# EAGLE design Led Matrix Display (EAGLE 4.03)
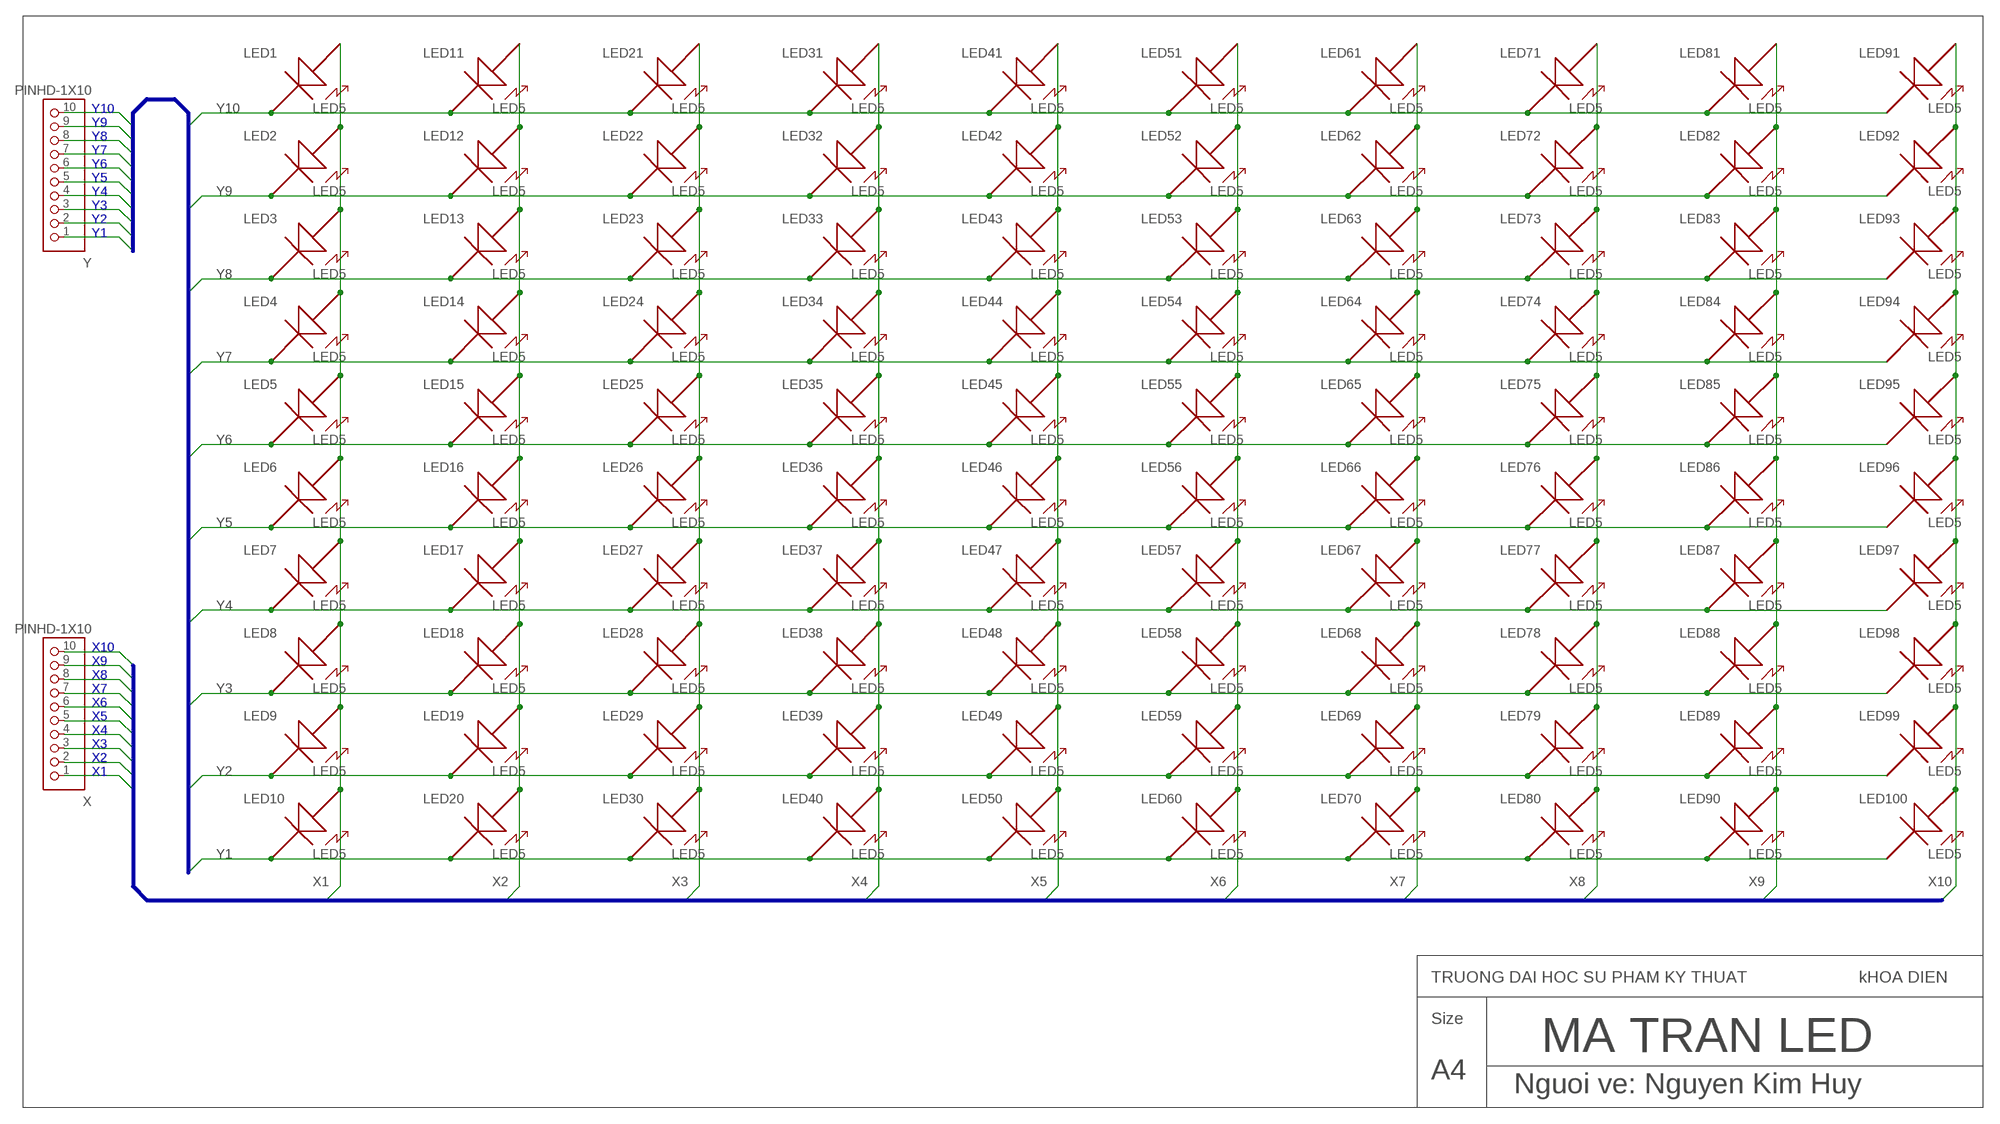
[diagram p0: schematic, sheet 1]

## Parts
LED1  LED5  [LED5]
LED2  LED5  [LED5]
LED3  LED5  [LED5]
LED4  LED5  [LED5]
LED5  LED5  [LED5]
LED6  LED5  [LED5]
LED7  LED5  [LED5]
LED8  LED5  [LED5]
LED9  LED5  [LED5]
LED10  LED5  [LED5]
LED11  LED5  [LED5]
LED12  LED5  [LED5]
LED13  LED5  [LED5]
LED14  LED5  [LED5]
LED15  LED5  [LED5]
LED16  LED5  [LED5]
LED17  LED5  [LED5]
LED18  LED5  [LED5]
LED19  LED5  [LED5]
LED20  LED5  [LED5]
LED21  LED5  [LED5]
LED22  LED5  [LED5]
LED23  LED5  [LED5]
LED24  LED5  [LED5]
LED25  LED5  [LED5]
LED26  LED5  [LED5]
LED27  LED5  [LED5]
LED28  LED5  [LED5]
LED29  LED5  [LED5]
LED30  LED5  [LED5]
LED31  LED5  [LED5]
LED32  LED5  [LED5]
LED33  LED5  [LED5]
LED34  LED5  [LED5]
LED35  LED5  [LED5]
LED36  LED5  [LED5]
LED37  LED5  [LED5]
LED38  LED5  [LED5]
LED39  LED5  [LED5]
LED40  LED5  [LED5]
LED41  LED5  [LED5]
LED42  LED5  [LED5]
LED43  LED5  [LED5]
LED44  LED5  [LED5]
LED45  LED5  [LED5]
LED46  LED5  [LED5]
LED47  LED5  [LED5]
LED48  LED5  [LED5]
LED49  LED5  [LED5]
LED50  LED5  [LED5]
LED51  LED5  [LED5]
LED52  LED5  [LED5]
LED53  LED5  [LED5]
LED54  LED5  [LED5]
LED55  LED5  [LED5]
LED56  LED5  [LED5]
LED57  LED5  [LED5]
LED58  LED5  [LED5]
LED59  LED5  [LED5]
LED60  LED5  [LED5]
LED61  LED5  [LED5]
LED62  LED5  [LED5]
LED63  LED5  [LED5]
LED64  LED5  [LED5]
LED65  LED5  [LED5]
LED66  LED5  [LED5]
LED67  LED5  [LED5]
LED68  LED5  [LED5]
LED69  LED5  [LED5]
LED70  LED5  [LED5]
LED71  LED5  [LED5]
LED72  LED5  [LED5]
LED73  LED5  [LED5]
LED74  LED5  [LED5]
LED75  LED5  [LED5]
LED76  LED5  [LED5]
LED77  LED5  [LED5]
LED78  LED5  [LED5]
LED79  LED5  [LED5]
LED80  LED5  [LED5]
LED81  LED5  [LED5]
LED82  LED5  [LED5]
LED83  LED5  [LED5]
LED84  LED5  [LED5]
LED85  LED5  [LED5]
LED86  LED5  [LED5]
LED87  LED5  [LED5]
LED88  LED5  [LED5]
LED89  LED5  [LED5]
LED90  LED5  [LED5]
LED91  LED5  [LED5]
LED92  LED5  [LED5]
LED93  LED5  [LED5]
LED94  LED5  [LED5]
LED95  LED5  [LED5]
LED96  LED5  [LED5]
LED97  LED5  [LED5]
LED98  LED5  [LED5]
LED99  LED5  [LED5]
LED100  LED5  [LED5]
X  PINHD-1X10  [1X10]
Y  PINHD-1X10  [1X10]

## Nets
X1: LED1.A(ANODE) LED2.A(ANODE) LED3.A(ANODE) LED4.A(ANODE) LED5.A(ANODE) LED6.A(ANODE) LED7.A(ANODE) LED8.A(ANODE) LED9.A(ANODE) LED10.A(ANODE) X.1
X2: LED11.A(ANODE) LED12.A(ANODE) LED13.A(ANODE) LED14.A(ANODE) LED15.A(ANODE) LED16.A(ANODE) LED17.A(ANODE) LED18.A(ANODE) LED19.A(ANODE) LED20.A(ANODE) X.2
X3: LED21.A(ANODE) LED22.A(ANODE) LED23.A(ANODE) LED24.A(ANODE) LED25.A(ANODE) LED26.A(ANODE) LED27.A(ANODE) LED28.A(ANODE) LED29.A(ANODE) LED30.A(ANODE) X.3
X4: LED31.A(ANODE) LED32.A(ANODE) LED33.A(ANODE) LED34.A(ANODE) LED35.A(ANODE) LED36.A(ANODE) LED37.A(ANODE) LED38.A(ANODE) LED39.A(ANODE) LED40.A(ANODE) X.4
X5: LED41.A(ANODE) LED42.A(ANODE) LED43.A(ANODE) LED44.A(ANODE) LED45.A(ANODE) LED46.A(ANODE) LED47.A(ANODE) LED48.A(ANODE) LED49.A(ANODE) LED50.A(ANODE) X.5
X6: LED51.A(ANODE) LED52.A(ANODE) LED53.A(ANODE) LED54.A(ANODE) LED55.A(ANODE) LED56.A(ANODE) LED57.A(ANODE) LED58.A(ANODE) LED59.A(ANODE) LED60.A(ANODE) X.6
X7: LED61.A(ANODE) LED62.A(ANODE) LED63.A(ANODE) LED64.A(ANODE) LED65.A(ANODE) LED66.A(ANODE) LED67.A(ANODE) LED68.A(ANODE) LED69.A(ANODE) LED70.A(ANODE) X.7
X8: LED71.A(ANODE) LED72.A(ANODE) LED73.A(ANODE) LED74.A(ANODE) LED75.A(ANODE) LED76.A(ANODE) LED77.A(ANODE) LED78.A(ANODE) LED79.A(ANODE) LED80.A(ANODE) X.8
X9: LED81.A(ANODE) LED82.A(ANODE) LED83.A(ANODE) LED84.A(ANODE) LED85.A(ANODE) LED86.A(ANODE) LED87.A(ANODE) LED88.A(ANODE) LED89.A(ANODE) LED90.A(ANODE) X.9
X10: LED91.A(ANODE) LED92.A(ANODE) LED93.A(ANODE) LED94.A(ANODE) LED95.A(ANODE) LED96.A(ANODE) LED97.A(ANODE) LED98.A(ANODE) LED99.A(ANODE) LED100.A(ANODE) X.10
Y1: LED10.K(CATHODE) LED20.K(CATHODE) LED30.K(CATHODE) LED40.K(CATHODE) LED50.K(CATHODE) LED60.K(CATHODE) LED70.K(CATHODE) LED80.K(CATHODE) LED90.K(CATHODE) LED100.K(CATHODE) Y.1
Y2: LED9.K(CATHODE) LED19.K(CATHODE) LED29.K(CATHODE) LED39.K(CATHODE) LED49.K(CATHODE) LED59.K(CATHODE) LED69.K(CATHODE) LED79.K(CATHODE) LED89.K(CATHODE) LED99.K(CATHODE) Y.2
Y3: LED8.K(CATHODE) LED18.K(CATHODE) LED28.K(CATHODE) LED38.K(CATHODE) LED48.K(CATHODE) LED58.K(CATHODE) LED68.K(CATHODE) LED78.K(CATHODE) LED88.K(CATHODE) LED98.K(CATHODE) Y.3
Y4: LED7.K(CATHODE) LED17.K(CATHODE) LED27.K(CATHODE) LED37.K(CATHODE) LED47.K(CATHODE) LED57.K(CATHODE) LED67.K(CATHODE) LED77.K(CATHODE) LED87.K(CATHODE) LED97.K(CATHODE) Y.4
Y5: LED6.K(CATHODE) LED16.K(CATHODE) LED26.K(CATHODE) LED36.K(CATHODE) LED46.K(CATHODE) LED56.K(CATHODE) LED66.K(CATHODE) LED76.K(CATHODE) LED86.K(CATHODE) LED96.K(CATHODE) Y.5
Y6: LED5.K(CATHODE) LED15.K(CATHODE) LED25.K(CATHODE) LED35.K(CATHODE) LED45.K(CATHODE) LED55.K(CATHODE) LED65.K(CATHODE) LED75.K(CATHODE) LED85.K(CATHODE) LED95.K(CATHODE) Y.6
Y7: LED4.K(CATHODE) LED14.K(CATHODE) LED24.K(CATHODE) LED34.K(CATHODE) LED44.K(CATHODE) LED54.K(CATHODE) LED64.K(CATHODE) LED74.K(CATHODE) LED84.K(CATHODE) LED94.K(CATHODE) Y.7
Y8: LED3.K(CATHODE) LED13.K(CATHODE) LED23.K(CATHODE) LED33.K(CATHODE) LED43.K(CATHODE) LED53.K(CATHODE) LED63.K(CATHODE) LED73.K(CATHODE) LED83.K(CATHODE) LED93.K(CATHODE) Y.8
Y9: LED2.K(CATHODE) LED12.K(CATHODE) LED22.K(CATHODE) LED32.K(CATHODE) LED42.K(CATHODE) LED52.K(CATHODE) LED62.K(CATHODE) LED72.K(CATHODE) LED82.K(CATHODE) LED92.K(CATHODE) Y.9
Y10: LED1.K(CATHODE) LED11.K(CATHODE) LED21.K(CATHODE) LED31.K(CATHODE) LED41.K(CATHODE) LED51.K(CATHODE) LED61.K(CATHODE) LED71.K(CATHODE) LED81.K(CATHODE) LED91.K(CATHODE) Y.10

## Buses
Y[1..10]
X[1..10]

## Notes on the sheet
- TRUONG DAI HOC SU PHAM KY THUAT | kHOA DIEN
- Size
- MA TRAN LED
- A4
- Nguoi ve: Nguyen Kim Huy

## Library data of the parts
LED1-LED100 = HUY:LED5
X Y = PINHEAD:PINHD-1X10

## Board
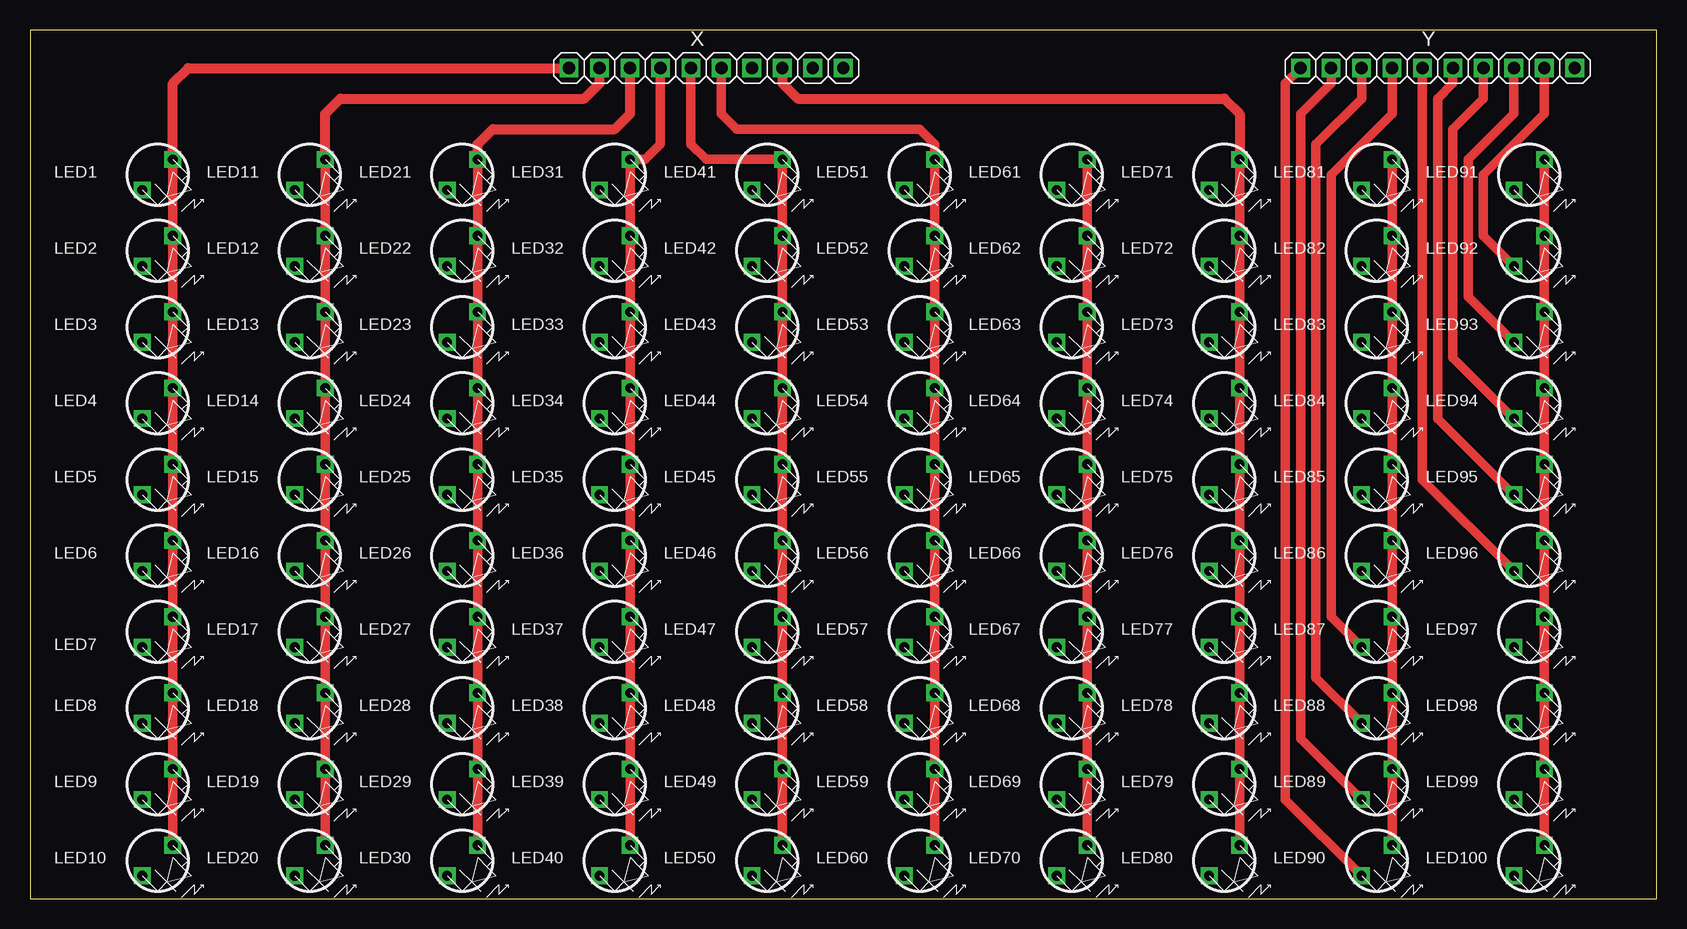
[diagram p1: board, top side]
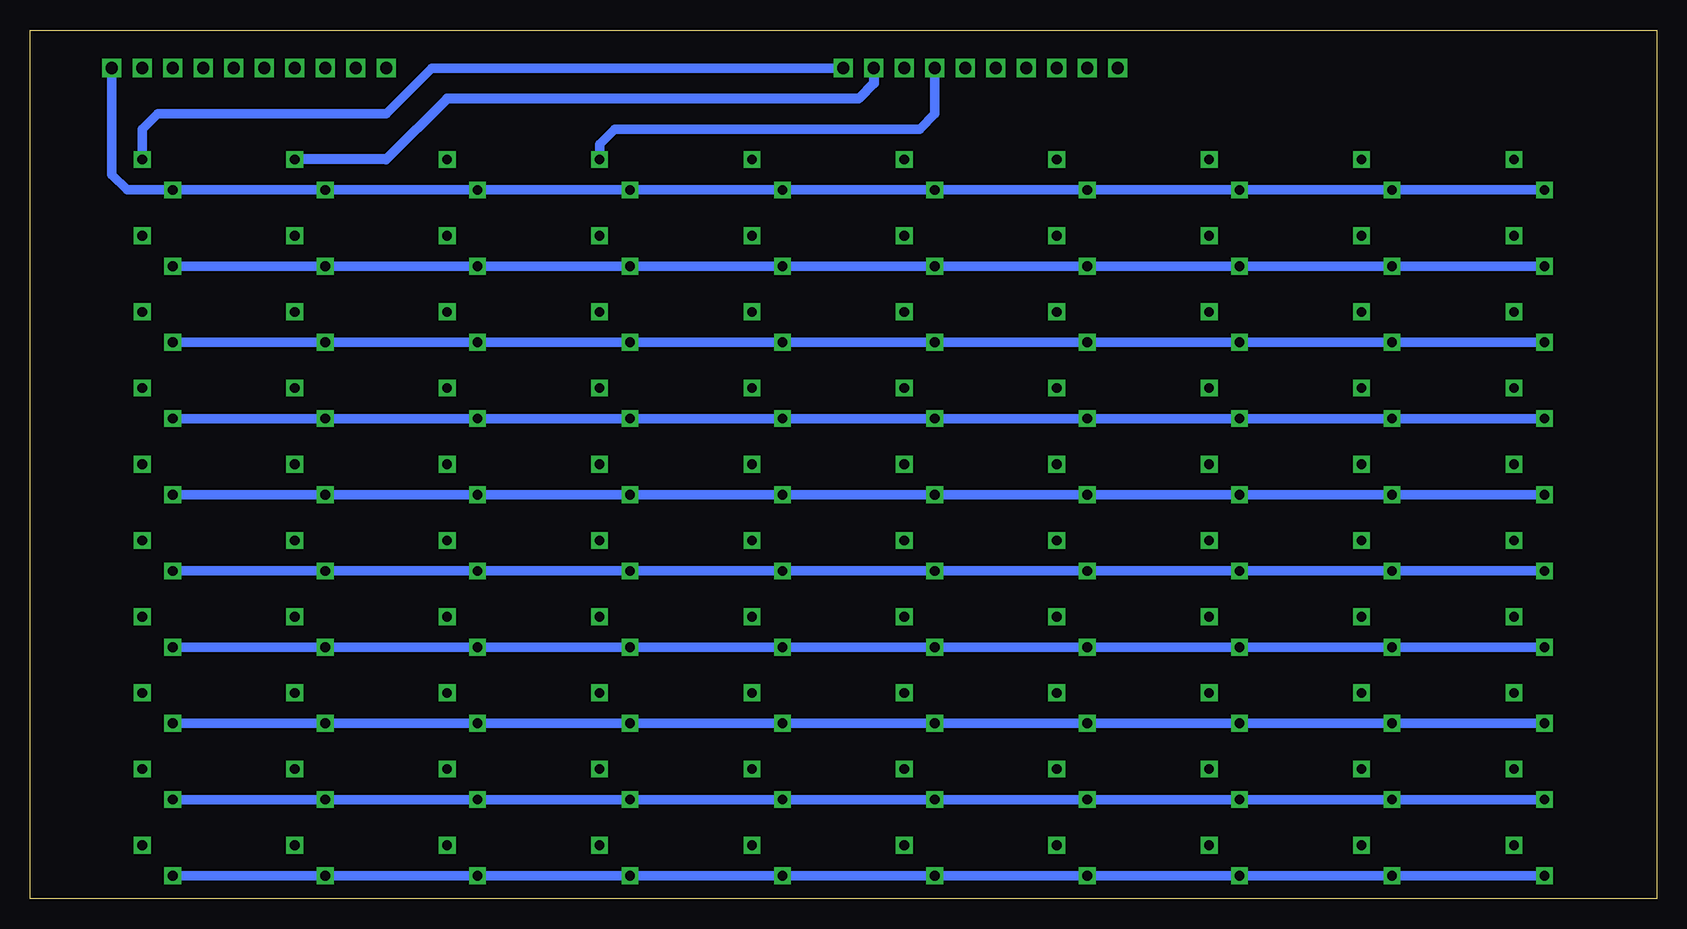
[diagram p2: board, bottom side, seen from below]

Size 135.56 x 72.38 mm. Coordinates in mm from the lower left corner, seen from the top.
Outline: 0,0 135.56,0 135.56,72.38 0,72.38 0,0
Copper layers used: Top, Bottom

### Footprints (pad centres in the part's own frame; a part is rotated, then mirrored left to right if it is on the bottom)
LED5 = drill 0.813 pad 1.397 square: A 2.54,2.54; K 0,0
1X10 = drill 1.016 pad 1.575 square: 1 -11.43,0; 2 -8.89,0; 3 -6.35,0; 4 -3.81,0; 5 -1.27,0; 6 1.27,0; 7 3.81,0; 8 6.35,0; 9 8.89,0; 10 11.43,0

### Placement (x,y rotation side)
LED1  9.36,59.05 0 top
LED2  9.36,52.7 0 top
LED3  9.36,46.35 0 top
LED4  9.36,40 0 top
LED5  9.36,33.65 0 top
LED6  9.36,27.3 0 top
LED7  9.36,20.95 0 top
LED8  9.36,14.6 0 top
LED9  9.36,8.25 0 top
LED10  9.36,1.9 0 top
LED11  22.06,59.05 0 top
LED12  22.06,52.7 0 top
LED13  22.06,46.35 0 top
LED14  22.06,40 0 top
LED15  22.06,33.65 0 top
LED16  22.06,27.3 0 top
LED17  22.06,20.95 0 top
LED18  22.06,14.6 0 top
LED19  22.06,8.25 0 top
LED20  22.06,1.9 0 top
LED21  34.76,59.05 0 top
LED22  34.76,52.7 0 top
LED23  34.76,46.35 0 top
LED24  34.76,40 0 top
LED25  34.76,33.65 0 top
LED26  34.76,27.3 0 top
LED27  34.76,20.95 0 top
LED28  34.76,14.6 0 top
LED29  34.76,8.25 0 top
LED30  34.76,1.9 0 top
LED31  47.46,59.05 0 top
LED32  47.46,52.7 0 top
LED33  47.46,46.35 0 top
LED34  47.46,40 0 top
LED35  47.46,33.65 0 top
LED36  47.46,27.3 0 top
LED37  47.46,20.95 0 top
LED38  47.46,14.6 0 top
LED39  47.46,8.25 0 top
LED40  47.46,1.9 0 top
LED41  60.16,59.05 0 top
LED42  60.16,52.7 0 top
LED43  60.16,46.35 0 top
LED44  60.16,40 0 top
LED45  60.16,33.65 0 top
LED46  60.16,27.3 0 top
LED47  60.16,20.95 0 top
LED48  60.16,14.6 0 top
LED49  60.16,8.25 0 top
LED50  60.16,1.9 0 top
LED51  72.86,59.05 0 top
LED52  72.86,52.7 0 top
LED53  72.86,46.35 0 top
LED54  72.86,40 0 top
LED55  72.86,33.65 0 top
LED56  72.86,27.3 0 top
LED57  72.86,20.95 0 top
LED58  72.86,14.6 0 top
LED59  72.86,8.25 0 top
LED60  72.86,1.9 0 top
LED61  85.56,59.05 0 top
LED62  85.56,52.7 0 top
LED63  85.56,46.35 0 top
LED64  85.56,40 0 top
LED65  85.56,33.65 0 top
LED66  85.56,27.3 0 top
LED67  85.56,20.95 0 top
LED68  85.56,14.6 0 top
LED69  85.56,8.25 0 top
LED70  85.56,1.9 0 top
LED71  98.26,59.05 0 top
LED72  98.26,52.7 0 top
LED73  98.26,46.35 0 top
LED74  98.26,40 0 top
LED75  98.26,33.65 0 top
LED76  98.26,27.3 0 top
LED77  98.26,20.95 0 top
LED78  98.26,14.6 0 top
LED79  98.26,8.25 0 top
LED80  98.26,1.9 0 top
LED81  110.96,59.05 0 top
LED82  110.96,52.7 0 top
LED83  110.96,46.35 0 top
LED84  110.96,40 0 top
LED85  110.96,33.65 0 top
LED86  110.96,27.3 0 top
LED87  110.96,20.95 0 top
LED88  110.96,14.6 0 top
LED89  110.96,8.25 0 top
LED90  110.96,1.9 0 top
LED91  123.66,59.05 0 top
LED92  123.66,52.7 0 top
LED93  123.66,46.35 0 top
LED94  123.66,40 0 top
LED95  123.66,33.65 0 top
LED96  123.66,27.3 0 top
LED97  123.66,20.95 0 top
LED98  123.66,14.6 0 top
LED99  123.66,8.25 0 top
LED100  123.66,1.9 0 top
X  56.35,69.21 0 top
Y  117.31,69.21 0 top

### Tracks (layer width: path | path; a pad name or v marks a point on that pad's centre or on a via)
X1
  Top 0.806: LED10.A LED9.A LED8.A LED7.A LED6.A LED5.A LED4.A LED3.A LED2.A LED1.A
  Top 0.813: LED1.A 11.9,67.94 13.17,69.21 X.1
X2
  Top 0.806: LED11.A LED12.A LED13.A LED14.A LED15.A LED16.A LED17.A LED18.A LED19.A LED20.A
  Top 0.813: LED11.A 24.6,65.4 25.87,66.67 46.19,66.67 47.46,67.94 X.2
X3
  Top 0.806: LED21.A LED22.A LED23.A LED24.A LED25.A LED26.A LED27.A LED28.A LED29.A LED30.A
  Top 0.813: LED21.A 37.3,62.86 38.57,64.13 48.73,64.13 50,65.4 X.3
X4
  Top 0.806: X.4 52.54,62.86 51.27,61.59 LED31.A LED32.A LED33.A LED34.A LED35.A LED36.A LED37.A LED38.A LED39.A LED40.A
X5
  Top 0.806: X.5 55.08,62.86 56.35,61.59 LED41.A LED42.A LED43.A LED44.A LED45.A LED46.A LED47.A LED48.A LED49.A LED50.A
X6
  Top 0.806: X.6 57.62,65.4 58.89,64.13 74.13,64.13 75.4,62.86 LED51.A LED52.A LED53.A LED54.A LED55.A LED56.A LED57.A LED58.A LED59.A LED60.A
X7
  Top 0.806: LED61.A LED62.A LED63.A LED64.A LED65.A LED66.A LED67.A LED68.A LED69.A LED70.A
  Bottom 0.806: X.7 60.16,65.4 61.43,64.13 86.83,64.13 88.1,62.86 LED61.A
X8
  Top 0.806: LED80.A LED79.A LED78.A LED77.A LED76.A LED75.A LED74.A LED73.A LED72.A LED71.A
  Top 0.813: X.8 62.7,67.94 63.97,66.67 99.53,66.67 100.8,65.4 LED71.A
X9
  Top 0.806: LED90.A LED89.A LED88.A LED87.A LED86.A LED85.A LED84.A LED83.A LED82.A LED81.A
  Bottom 0.813: X.9 65.24,67.94 66.51,66.67 100.8,66.67 105.88,61.59 LED81.A
X10
  Top 0.806: LED100.A LED99.A LED98.A LED97.A LED96.A LED95.A LED94.A LED93.A LED92.A LED91.A
  Bottom 0.806: X.10 102.07,69.21 105.88,65.4 124.93,65.4 126.2,64.13 LED91.A
Y1
  Top 0.806: Y.1 104.61,67.94 104.61,8.25 LED90.K
  Bottom 0.806: LED100.K LED90.K LED80.K LED70.K LED60.K LED50.K LED40.K LED30.K LED20.K LED10.K
Y2
  Top 0.806: Y.2 108.42,67.94 105.88,65.4 105.88,13.33 LED89.K
  Bottom 0.806: LED99.K LED89.K LED79.K LED69.K LED59.K LED49.K LED39.K LED29.K LED19.K LED9.K
Y3
  Top 0.806: Y.3 110.96,66.67 107.15,62.86 107.15,18.41 LED88.K
  Bottom 0.806: LED98.K LED88.K LED78.K LED68.K LED58.K LED48.K LED38.K LED28.K LED18.K LED8.K
Y4
  Top 0.806: Y.4 113.5,65.4 108.42,60.32 108.42,23.49 LED87.K
  Bottom 0.806: LED97.K LED87.K LED77.K LED67.K LED57.K LED47.K LED37.K LED27.K LED17.K LED7.K
Y5
  Top 0.806: Y.5 116.04,34.92 LED96.K
  Bottom 0.806: LED96.K LED86.K LED76.K LED66.K LED56.K LED46.K LED36.K LED26.K LED16.K LED6.K
Y6
  Top 0.806: Y.6 118.58,67.94 117.31,66.67 117.31,40 LED95.K
  Bottom 0.806: LED95.K LED85.K LED75.K LED65.K LED55.K LED45.K LED35.K LED25.K LED15.K LED5.K
Y7
  Top 0.806: Y.7 121.12,66.67 118.58,64.13 118.58,45.08 LED94.K
  Bottom 0.806: LED94.K LED84.K LED74.K LED64.K LED54.K LED44.K LED34.K LED24.K LED14.K LED4.K
Y8
  Top 0.806: Y.8 123.66,65.4 119.85,61.59 119.85,50.16 LED93.K
  Bottom 0.806: LED3.K LED13.K LED23.K LED33.K LED43.K LED53.K LED63.K LED73.K LED83.K LED93.K
Y9
  Top 0.806: Y.9 126.2,65.4 121.12,60.32 121.12,55.24 LED92.K
  Bottom 0.806: LED2.K LED12.K LED22.K LED32.K LED42.K LED52.K LED62.K LED72.K LED82.K LED92.K
Y10
  Bottom 0.806: LED1.K LED11.K LED21.K LED31.K LED41.K LED51.K LED61.K LED71.K LED81.K LED91.K 127.47,59.05 128.74,60.32 Y.10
